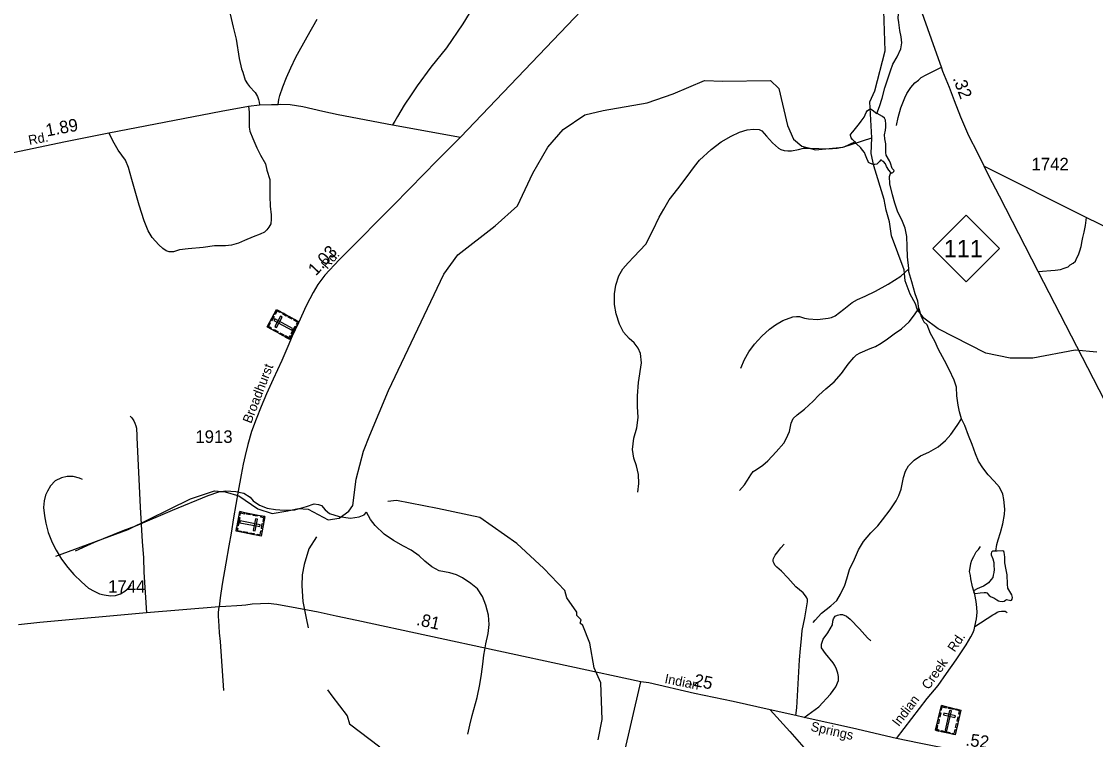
# Model space of a CAD drawing. Extents: x 2206922 to 2357709, y 510027 to 673830.
# Drawn here: x 2317208 to 2327936, y 539926 to 547095 of the extents above; entities that cross this region are included whole.
import ezdxf

# ---------------------------------------------------------------- set-up
doc = ezdxf.new("R2010")
doc.units = 0
for name, color, linetype in [('Exist Cultural Cemetery CELL', 7, 'Continuous'), ('Exist Hydrographic Creek Single Shore', 7, 'Continuous'), ('Exist Hydrographic Misc Water Feature', 7, 'Continuous'), ('Exist Hydrographic Pond Under 1500 Sq Ft', 7, 'Continuous'), ('Exist Road Non-System Type 51', 7, 'Continuous'), ('Exist Road Non-System Type 51 Label', 7, 'Continuous'), ('Exist Road Primary NC Attributed', 7, 'Continuous'), ('Exist Road Primary NC Service Mileage Hundredths English Label', 7, 'Continuous'), ('Exist Road Primary NC Shield CELL', 7, 'Continuous'), ('Exist Road Primary NC Shield Number Label', 7, 'Continuous'), ('Exist Road Secondary Mileage Hundredths English Label', 7, 'Continuous'), ('Exist Road Secondary Type 51 Attributed', 7, 'Continuous'), ('Exist Road Secondary Type 51 Label', 7, 'Continuous'), ('Exist Road Secondary Type 51 Number Label', 7, 'Continuous')]:
    doc.layers.add(name, color=color, linetype=linetype)

msp = doc.modelspace()

# ---------------------------------------------------------------- linework, layer by layer
at = {"layer": 'Exist Cultural Cemetery CELL'}
for points in [[(2319661, 544046), (2319757, 544220), (2319980, 544098), (2319884, 543923)], [(2319696, 544111), (2319721, 544156), (2319731, 544151), (2319706, 544105)], [(2319795, 544199), (2319789, 544190), (2319761, 544205), (2319741, 544170), (2319732, 544175), (2319757, 544220)], [(2319740, 544049), (2319756, 544040), (2319813, 544143), (2319797, 544152)], [(2319853, 544154), (2319815, 544175), (2319821, 544185), (2319859, 544164)], [(2319911, 544122), (2319873, 544143), (2319878, 544153), (2319916, 544132)], [(2319699, 544025), (2319704, 544035), (2319676, 544050), (2319695, 544086), (2319686, 544091), (2319661, 544046)], [(2319739, 544127), (2319730, 544111), (2319907, 544013), (2319916, 544030)], [(2319901, 543979), (2319942, 544053), (2319952, 544048), (2319911, 543974)], [(2319964, 544069), (2319954, 544074), (2319964, 544093), (2319929, 544113), (2319934, 544123), (2319980, 544098)], [(2319764, 543989), (2319726, 544010), (2319731, 544020), (2319769, 543999)], [(2319822, 543957), (2319784, 543978), (2319790, 543988), (2319828, 543967)], [(2319900, 543952), (2319890, 543958), (2319879, 543938), (2319844, 543958), (2319838, 543948), (2319884, 543923)], [(2319638, 542153), (2319601, 541958), (2319351, 542005), (2319388, 542201)], [(2319382, 542168), (2319393, 542166), (2319397, 542188), (2319437, 542180), (2319439, 542191), (2319388, 542201)], [(2319389, 542142), (2319373, 542059), (2319362, 542061), (2319378, 542144)], [(2319589, 542052), (2319593, 542070), (2319394, 542108), (2319390, 542089)], [(2319457, 542188), (2319499, 542180), (2319497, 542168), (2319455, 542176)], [(2319523, 542175), (2319566, 542167), (2319563, 542156), (2319521, 542164)], [(2319564, 542126), (2319546, 542129), (2319524, 542014), (2319542, 542010)], [(2319596, 542161), (2319594, 542150), (2319625, 542144), (2319618, 542104), (2319629, 542102), (2319638, 542153)], [(2319357, 542038), (2319369, 542035), (2319364, 542014), (2319404, 542006), (2319402, 541995), (2319351, 542005)], [(2319424, 542003), (2319467, 541995), (2319465, 541984), (2319422, 541992)], [(2319489, 541990), (2319532, 541982), (2319529, 541971), (2319487, 541979)], [(2319559, 541966), (2319561, 541977), (2319592, 541971), (2319600, 542011), (2319611, 542009), (2319601, 541958)], [(2319625, 542080), (2319615, 542030), (2319604, 542032), (2319613, 542083)], [(2326398, 540265), (2326592, 540220), (2326533, 539972), (2326339, 540018)], [(2326371, 540151), (2326381, 540193), (2326392, 540191), (2326382, 540148)], [(2326388, 540223), (2326399, 540221), (2326406, 540252), (2326446, 540243), (2326448, 540253), (2326398, 540265)], [(2326422, 540190), (2326418, 540172), (2326532, 540145), (2326537, 540163)], [(2326497, 540212), (2326479, 540216), (2326433, 540019), (2326451, 540014)], [(2326470, 540248), (2326520, 540236), (2326518, 540225), (2326467, 540237)], [(2326582, 540178), (2326571, 540180), (2326578, 540211), (2326539, 540221), (2326541, 540232), (2326592, 540220)], [(2326372, 540010), (2326374, 540021), (2326353, 540026), (2326362, 540066), (2326351, 540068), (2326339, 540018)], [(2326355, 540086), (2326365, 540128), (2326376, 540125), (2326367, 540083)], [(2326539, 540045), (2326549, 540087), (2326560, 540084), (2326550, 540042)], [(2326554, 540109), (2326564, 540151), (2326575, 540149), (2326565, 540106)], [(2326398, 540016), (2326481, 539996), (2326478, 539985), (2326395, 540004)], [(2326501, 539979), (2326504, 539991), (2326525, 539986), (2326534, 540025), (2326545, 540022), (2326533, 539972)]]:
    msp.add_lwpolyline(points, close=True, dxfattribs=at)
at = {"layer": 'Exist Hydrographic Creek Single Shore'}
for points in [[(2325703, 545935), (2325682, 546292), (2325731, 546402), (2325835, 546803), (2325822, 547203), (2325779, 547418), (2325769, 547575), (2325732, 547768)], [(2317552, 541757), (2318274, 542022), (2318895, 542329), (2319136, 542408), (2319244, 542399), (2319378, 542359), (2319570, 542229), (2319713, 542182), (2319870, 542208), (2319971, 542232), (2320071, 542226), (2320272, 542119), (2320380, 542137), (2320478, 542206), (2320519, 542264), (2320550, 542524), (2320623, 542806), (2320688, 542966), (2320874, 543410), (2321427, 544574), (2321567, 544767), (2321939, 545054), (2322162, 545254), (2322317, 545582), (2322464, 545840), (2322620, 546017), (2322835, 546164), (2323018, 546207), (2323458, 546284), (2323716, 546373), (2324031, 546507), (2324214, 546501), (2324689, 546507), (2324773, 546426), (2324860, 546058), (2324920, 545920), (2325004, 545851), (2325138, 545813), (2325412, 545841), (2325703, 545935)], [(2327950, 543794), (2327733, 543815), (2327309, 543735), (2327084, 543733), (2326842, 543782), (2326365, 544025), (2326222, 544134), (2326154, 544224), (2326137, 544275), (2326086, 544372), (2326035, 544507), (2326025, 544615), (2325897, 544955), (2325879, 545095), (2325844, 545212), (2325826, 545319), (2325723, 545653), (2325696, 545777), (2325703, 545935)]]:
    msp.add_lwpolyline(points, dxfattribs=at)
at = {"layer": 'Exist Hydrographic Misc Water Feature'}
for points in [[(2325752, 546176), (2325779, 546248), (2325804, 546329), (2325831, 546433), (2325864, 546533), (2325889, 546603), (2325912, 546668), (2325956, 546744), (2325993, 546823), (2326000, 546883), (2325996, 546941), (2325983, 547005), (2325970, 547084), (2325965, 547128), (2325970, 547216), (2325978, 547308), (2325979, 547378), (2325984, 547450), (2325993, 547528), (2325991, 547598), (2325968, 547660), (2325925, 547721), (2325895, 547765)], [(2325531, 545894), (2325509, 545918), (2325495, 545934), (2325488, 545956), (2325490, 545966), (2325512, 545992), (2325579, 546078), (2325597, 546099), (2325626, 546141), (2325646, 546185), (2325660, 546205), (2325676, 546217), (2325687, 546222), (2325705, 546214), (2325752, 546176)], [(2325892, 545586), (2325900, 545582), (2325912, 545586), (2325918, 545593), (2325922, 545598), (2325924, 545608), (2325916, 545618), (2325906, 545628), (2325889, 545682), (2325879, 545704), (2325846, 545762), (2325842, 545787), (2325841, 545873), (2325831, 545923), (2325830, 545963), (2325838, 546009), (2325841, 546039), (2325841, 546071), (2325837, 546111), (2325829, 546129), (2325810, 546145), (2325756, 546176), (2325752, 546176)], [(2323366, 542396), (2323373, 542481), (2323372, 542571), (2323351, 542658), (2323325, 542736), (2323311, 542822), (2323324, 542934), (2323355, 543038), (2323368, 543140), (2323361, 543250), (2323360, 543358), (2323372, 543492), (2323402, 543688), (2323391, 543780), (2323369, 543832), (2323328, 543888), (2323277, 543931), (2323223, 543992), (2323180, 544072), (2323147, 544175), (2323132, 544271), (2323133, 544375), (2323146, 544463), (2323175, 544555), (2323214, 544626), (2323267, 544686), (2323326, 544745), (2323443, 544872), (2323514, 545007), (2323578, 545141), (2323624, 545222), (2323678, 545316), (2323763, 545425), (2323858, 545546), (2323929, 545647), (2323980, 545711), (2324097, 545817), (2324198, 545894), (2324297, 545949), (2324381, 545990), (2324456, 546014), (2324519, 546021), (2324576, 546018), (2324604, 546002), (2324651, 545951), (2324709, 545883), (2324770, 545830), (2324794, 545818), (2324826, 545807), (2324864, 545805), (2324900, 545805), (2324968, 545818), (2325018, 545829)], [(2325018, 545829), (2325028, 545829), (2325086, 545831), (2325174, 545826), (2325266, 545825), (2325356, 545830), (2325424, 545845), (2325531, 545894)], [(2325892, 545586), (2325872, 545610), (2325850, 545647), (2325840, 545673), (2325819, 545697), (2325809, 545701), (2325799, 545709), (2325787, 545711), (2325781, 545701), (2325761, 545679), (2325751, 545672), (2325733, 545666), (2325715, 545666), (2325689, 545678), (2325676, 545684), (2325669, 545688), (2325665, 545696), (2325653, 545727), (2325638, 545761), (2325628, 545787), (2325610, 545811), (2325593, 545835), (2325547, 545878), (2325535, 545892), (2325531, 545894)], [(2326070, 544624), (2326071, 544630), (2326059, 544744), (2326056, 544850), (2326051, 544950), (2326036, 545032), (2326007, 545099), (2325958, 545201), (2325933, 545282), (2325909, 545364), (2325883, 545474), (2325877, 545548), (2325892, 545586)], [(2324392, 543635), (2324431, 543719), (2324472, 543796), (2324531, 543872), (2324603, 543953), (2324681, 544022), (2324741, 544067), (2324812, 544109), (2324914, 544146), (2324948, 544151), (2324980, 544149), (2325028, 544134), (2325071, 544128), (2325160, 544121), (2325266, 544132), (2325300, 544141), (2325336, 544157), (2325421, 544222), (2325504, 544289), (2325560, 544319), (2325637, 544354), (2325739, 544403), (2325865, 544473), (2325993, 544552), (2326070, 544624)], [(2326173, 544230), (2326162, 544304), (2326135, 544377), (2326100, 544497), (2326071, 544595), (2326070, 544624)], [(2324379, 542413), (2324429, 542468), (2324460, 542516), (2324494, 542569), (2324515, 542601), (2324551, 542623), (2324612, 542664), (2324662, 542708), (2324747, 542797), (2324822, 542884), (2324847, 542928), (2324881, 543001), (2324896, 543085), (2324917, 543131), (2324955, 543169), (2325028, 543224), (2325117, 543305), (2325171, 543363), (2325242, 543428), (2325327, 543497), (2325398, 543582), (2325465, 543675), (2325522, 543741), (2325548, 543768), (2325584, 543788), (2325684, 543829), (2325737, 543851), (2325795, 543882), (2325858, 543926), (2325926, 543975), (2325997, 544028), (2326074, 544095), (2326127, 544165), (2326173, 544230)], [(2326173, 544230), (2326196, 544148), (2326222, 544098), (2326254, 544067)], [(2326596, 543127), (2326576, 543197), (2326563, 543265), (2326552, 543357), (2326547, 543445), (2326526, 543514), (2326473, 543621), (2326428, 543711), (2326369, 543820), (2326332, 543902), (2326287, 543981), (2326254, 544067)], [(2325117, 541096), (2325135, 541118), (2325200, 541187), (2325291, 541260), (2325351, 541314), (2325390, 541377), (2325433, 541467), (2325452, 541531), (2325479, 541624), (2325528, 541728), (2325569, 541821), (2325618, 541903), (2325693, 541988), (2325762, 542059), (2325808, 542119), (2325884, 542220), (2325946, 542308), (2325973, 542363), (2325994, 542425), (2326019, 542541), (2326039, 542607), (2326068, 542659), (2326125, 542716), (2326187, 542759), (2326270, 542796), (2326364, 542849), (2326437, 542913), (2326492, 542970), (2326555, 543063), (2326596, 543127)], [(2326942, 541805), (2326950, 541873), (2326963, 541920), (2326988, 541994), (2327009, 542080), (2327028, 542174), (2327032, 542226), (2327021, 542322), (2327010, 542376), (2326977, 542445), (2326923, 542507), (2326863, 542570), (2326810, 542637), (2326767, 542705), (2326738, 542777), (2326703, 542870), (2326668, 542960), (2326631, 543060), (2326596, 543127)], [(2317818, 542523), (2317789, 542536), (2317723, 542553), (2317665, 542553), (2317608, 542538), (2317546, 542509), (2317498, 542459), (2317469, 542407), (2317449, 542365), (2317434, 542309), (2317429, 542242), (2317438, 542161), (2317450, 542085), (2317476, 541993), (2317516, 541893), (2317555, 541816), (2317608, 541727), (2317671, 541644), (2317732, 541574), (2317807, 541499), (2317877, 541436), (2317934, 541407), (2317986, 541381), (2318034, 541372), (2318096, 541362), (2318146, 541365), (2318196, 541381), (2318242, 541408), (2318281, 541440), (2318303, 541466)], [(2317749, 541810), (2317936, 541898), (2318223, 542013), (2318350, 542060), (2318716, 542215), (2319074, 542364), (2319178, 542399), (2319250, 542410), (2319350, 542403), (2319428, 542386), (2319494, 542345), (2319521, 542309), (2319585, 542266), (2319663, 542237), (2319744, 542222), (2319832, 542217), (2319940, 542220), (2320055, 542253), (2320131, 542278), (2320175, 542272), (2320205, 542261), (2320242, 542219), (2320284, 542183), (2320380, 542152), (2320494, 542136), (2320582, 542151), (2320632, 542171), (2320654, 542197)], [(2321667, 539979), (2321686, 540070), (2321709, 540166), (2321761, 540346), (2321788, 540475), (2321802, 540579), (2321817, 540677), (2321828, 540767), (2321838, 540823), (2321847, 540881), (2321870, 540985), (2321879, 541075), (2321872, 541169), (2321847, 541269), (2321812, 541354), (2321763, 541430), (2321695, 541483), (2321614, 541542), (2321554, 541569), (2321487, 541591), (2321379, 541611), (2321307, 541651), (2321237, 541708), (2321180, 541761), (2321099, 541816), (2321025, 541855), (2320924, 541912), (2320830, 541977), (2320741, 542064), (2320693, 542122), (2320654, 542197)], [(2320156, 541950), (2320080, 541831), (2320032, 541675), (2320013, 541569), (2320010, 541459), (2320019, 541303), (2320051, 541139), (2320072, 541040)], [(2326942, 541805), (2326906, 541805), (2326897, 541797), (2326893, 541783), (2326893, 541771), (2326911, 541731), (2326920, 541695), (2326922, 541665), (2326923, 541623), (2326919, 541595), (2326915, 541567), (2326910, 541543), (2326894, 541523), (2326866, 541491), (2326854, 541481), (2326819, 541458), (2326776, 541442), (2326755, 541432), (2326725, 541413), (2326719, 541401), (2326723, 541391), (2326733, 541385), (2326783, 541392), (2326825, 541394), (2326839, 541395), (2326851, 541391), (2326875, 541363), (2326895, 541349), (2326921, 541340), (2326950, 541322), (2326966, 541312), (2326982, 541308), (2327004, 541304), (2327024, 541307), (2327036, 541319), (2327046, 541323), (2327062, 541321), (2327078, 541317), (2327090, 541315), (2327098, 541318), (2327104, 541328), (2327106, 541343), (2327103, 541357), (2327099, 541371), (2327079, 541405), (2327062, 541437), (2327058, 541477), (2327053, 541569), (2327045, 541619), (2327032, 541690), (2327031, 541746), (2327027, 541772), (2327023, 541794), (2327019, 541804), (2327012, 541810), (2326954, 541807), (2326942, 541805)]]:
    msp.add_lwpolyline(points, dxfattribs=at)
at = {"layer": 'Exist Hydrographic Pond Under 1500 Sq Ft'}
for points in [[(2322969, 539924), (2323009, 540126), (2322996, 540493), (2322928, 540641), (2322884, 540889), (2322815, 541063), (2322790, 541088), (2322798, 541122), (2322756, 541163), (2322756, 541199), (2322654, 541339), (2322637, 541414), (2322426, 541635), (2322157, 541883), (2321788, 542144), (2321362, 542232), (2320953, 542311), (2320869, 542301)], [(2320265, 540422), (2320307, 540362), (2320460, 540164), (2320485, 540083), (2320787, 539853)]]:
    msp.add_lwpolyline(points, dxfattribs=at)
at = {"layer": 'Exist Road Non-System Type 51'}
for points in [[(2319181, 548304), (2319229, 547748), (2319239, 547499), (2319261, 547353), (2319270, 547265), (2319293, 547170), (2319324, 547040), (2319352, 546918), (2319381, 546726), (2319407, 546622), (2319414, 546605), (2319419, 546588), (2319441, 546511), (2319465, 546473), (2319485, 546446), (2319541, 546385), (2319567, 546345), (2319576, 546317), (2319581, 546290), (2319586, 546262)], [(2321754, 547294), (2321617, 547071), (2321455, 546833), (2321296, 546638), (2321161, 546453), (2321099, 546364), (2321031, 546260), (2320965, 546148), (2320938, 546101), (2320914, 546064)], [(2319771, 546268), (2319780, 546316), (2319789, 546357), (2319818, 546444), (2319855, 546537), (2319898, 546632), (2319950, 546738), (2320063, 546943), (2320160, 547118)], [(2325949, 546056), (2325965, 546138), (2325992, 546232), (2326031, 546333), (2326050, 546377), (2326091, 546435), (2326131, 546482), (2326169, 546510), (2326196, 546536), (2326244, 546561), (2326290, 546585), (2326399, 546638)], [(2319475, 546250), (2319481, 546189), (2319481, 546118), (2319481, 546068), (2319481, 546040), (2319488, 545999), (2319519, 545926), (2319559, 545833), (2319597, 545759), (2319645, 545673), (2319660, 545610), (2319688, 545517), (2319688, 545451), (2319688, 545350), (2319693, 545251), (2319703, 545165), (2319703, 545122), (2319698, 545074), (2319680, 545042), (2319658, 545016), (2319635, 544991), (2319592, 544971), (2319524, 544946), (2319435, 544908), (2319377, 544882), (2319307, 544862), (2319246, 544855), (2319135, 544855), (2319024, 544839), (2318872, 544824), (2318786, 544814), (2318756, 544804), (2318728, 544796), (2318683, 544796), (2318652, 544804), (2318620, 544829), (2318579, 544865), (2318514, 544940), (2318473, 545004), (2318435, 545105), (2318385, 545261), (2318311, 545517), (2318276, 545638), (2318248, 545709), (2318175, 545810), (2318122, 545903), (2318102, 545946), (2318082, 545982)], [(2327362, 544600), (2327534, 544612), (2327588, 544618), (2327624, 544633), (2327662, 544647), (2327684, 544665), (2327713, 544682), (2327735, 544702), (2327749, 544734), (2327767, 544764), (2327778, 544806), (2327792, 544850), (2327803, 544904), (2327809, 544940), (2327822, 544991), (2327835, 545057), (2327846, 545139)], [(2318293, 543155), (2318309, 543139), (2318329, 543109), (2318341, 543084), (2318352, 543058), (2318356, 543034), (2318356, 543006), (2318360, 542988), (2318361, 542942), (2318394, 542245), (2318414, 541903), (2318426, 541741), (2318430, 541597), (2318458, 541192)], [(2324942, 540166), (2324952, 540244), (2324979, 540720), (2324988, 540836), (2324998, 540930), (2325007, 541013), (2325032, 541142), (2325052, 541262), (2325060, 541302), (2325058, 541324), (2325053, 541340), (2325041, 541359), (2325016, 541389), (2324942, 541452), (2324862, 541542), (2324799, 541607), (2324752, 541646), (2324734, 541666), (2324725, 541685), (2324717, 541702), (2324717, 541719), (2324720, 541734), (2324735, 541766), (2324762, 541800), (2324794, 541840), (2324826, 541877)], [(2326731, 541055), (2326748, 541131), (2326754, 541193), (2326751, 541243), (2326744, 541303), (2326732, 541375), (2326707, 541451), (2326690, 541532), (2326688, 541564), (2326679, 541602), (2326683, 541640), (2326690, 541682), (2326700, 541716), (2326720, 541754), (2326743, 541799), (2326767, 541823), (2326788, 541853)], [(2319230, 540416), (2319197, 540904), (2319187, 540990), (2319184, 541058), (2319180, 541112), (2319177, 541156), (2319177, 541194), (2319183, 541250)], [(2325027, 540147), (2325172, 540251), (2325290, 540380), (2325343, 540452), (2325369, 540514), (2325369, 540554), (2325361, 540590), (2325349, 540629), (2325331, 540666), (2325315, 540691), (2325238, 540784), (2325199, 540843), (2325198, 540877), (2325215, 540928), (2325264, 540991), (2325308, 541070), (2325313, 541108), (2325319, 541132), (2325336, 541158), (2325359, 541169), (2325384, 541174), (2325409, 541174), (2325449, 541158), (2325487, 541128), (2325578, 541030), (2325659, 540941), (2325691, 540911)], [(2326731, 541055), (2326910, 541171), (2326931, 541181), (2326955, 541199), (2326973, 541204), (2326997, 541206), (2327015, 541208), (2327033, 541208), (2327055, 541195)], [(2325947, 539937), (2326253, 540334), (2326364, 540465), (2326448, 540586), (2326543, 540723), (2326643, 540872), (2326692, 540951), (2326710, 540989), (2326723, 541021), (2326731, 541055)]]:
    msp.add_lwpolyline(points, dxfattribs=at)
at = {"layer": 'Exist Road Primary NC Attributed'}
for points in [[(2326825, 545650), (2326762, 545779), (2326670, 545954), (2326592, 546141), (2326527, 546302), (2326477, 546435), (2326412, 546596), (2326399, 546638), (2326335, 546816), (2326188, 547229)], [(2328736, 541917), (2328193, 542992), (2327362, 544600), (2326977, 545351), (2326872, 545554), (2326825, 545650)]]:
    msp.add_lwpolyline(points, dxfattribs=at)
at = {"layer": 'Exist Road Primary NC Shield CELL'}
msp.add_lwpolyline([(2326311, 544830), (2326644, 545163), (2326977, 544830), (2326644, 544497)], close=True, dxfattribs=at)
at = {"layer": 'Exist Road Secondary Type 51 Attributed'}
for points in [[(2325185, 550826), (2325127, 550648), (2325122, 550633), (2325044, 550436), (2324919, 550096), (2324786, 549758), (2324523, 549115), (2324348, 548731), (2324256, 548522), (2324195, 548426), (2324124, 548330), (2324056, 548269), (2323981, 548202), (2323883, 548136), (2323784, 548086), (2323681, 548040), (2323593, 547995), (2323530, 547955), (2323475, 547909), (2323371, 547803), (2321593, 545939)], [(2316616, 545681), (2317649, 545898), (2318082, 545982), (2319203, 546200), (2319475, 546250), (2319586, 546262), (2319707, 546267), (2319771, 546268), (2319799, 546269), (2319893, 546265), (2320018, 546245), (2320217, 546201), (2320373, 546168), (2320914, 546064), (2321593, 545939)], [(2321593, 545939), (2321365, 545709), (2321221, 545563), (2321089, 545432), (2320913, 545250), (2320764, 545101), (2320596, 544929), (2320381, 544714), (2320239, 544562), (2320167, 544468), (2320121, 544388), (2320087, 544325), (2320050, 544250), (2320021, 544188), (2319974, 544086), (2319913, 543952), (2319868, 543849), (2319810, 543711), (2319721, 543523), (2319657, 543378), (2319601, 543252), (2319553, 543126), (2319507, 543003), (2319469, 542870), (2319441, 542763), (2319422, 542676), (2319403, 542568), (2319372, 542406), (2319350, 542271), (2319325, 542141), (2319302, 541985), (2319278, 541860), (2319248, 541686), (2319212, 541478), (2319192, 541340), (2319183, 541250)], [(2326825, 545650), (2327846, 545139), (2328564, 544789), (2328690, 544732), (2328765, 544687), (2328821, 544654), (2328896, 544606), (2328986, 544550), (2329056, 544505), (2329129, 544450), (2329186, 544392), (2329246, 544314), (2329327, 544202), (2329503, 543920), (2329704, 543619), (2329999, 543251), (2330253, 542932), (2330281, 542888), (2330334, 542807), (2330381, 542736), (2330407, 542674), (2330432, 542603), (2330459, 542525), (2330473, 542445)], [(2319183, 541250), (2318458, 541192), (2317390, 541093), (2317177, 541070)], [(2323395, 540503), (2320557, 541114), (2320351, 541158), (2320173, 541196), (2320065, 541217), (2319960, 541238), (2319758, 541274), (2319673, 541283), (2319596, 541281), (2319513, 541276), (2319448, 541269), (2319409, 541265), (2319359, 541261), (2319251, 541254), (2319183, 541250)], [(2322793, 537900), (2323395, 540503)], [(2324685, 540223), (2324318, 540304), (2323929, 540385), (2323473, 540491), (2323395, 540503)], [(2324685, 540223), (2324882, 540006), (2325023, 539847), (2325151, 539716), (2325264, 539593), (2325530, 539359), (2325618, 539290), (2325714, 539206), (2325788, 539151), (2325856, 539100), (2325969, 539014), (2326124, 538893), (2326335, 538725), (2326576, 538539), (2326632, 538495)], [(2327406, 539803), (2327343, 539794), (2327190, 539783), (2327028, 539776), (2326939, 539783), (2326754, 539796), (2326612, 539810), (2326486, 539830), (2326342, 539855), (2326176, 539890), (2325947, 539937), (2325510, 540040), (2325027, 540147), (2324942, 540166), (2324685, 540223)]]:
    msp.add_lwpolyline(points, dxfattribs=at)

# ---------------------------------------------------------------- texts
at = {"layer": 'Exist Road Non-System Type 51 Label'}
for s, rotation, p in [('Rd.', 56.0448, (2326530, 540792)), ('Creek', 55.0939, (2326270, 540417)), ('Indian', 52.4028, (2325971, 540049))]:
    msp.add_text(s, height=95, rotation=rotation, dxfattribs=at).set_placement(p)
at = {"layer": 'Exist Road Primary NC Service Mileage Hundredths English Label'}
msp.add_text('.32', height=125, rotation=290.3959, dxfattribs=at).set_placement((2326509, 546528))
at = {"layer": 'Exist Road Primary NC Shield Number Label'}
msp.add_text('111', height=175, dxfattribs=at).set_placement((2326420, 544740))
at = {"layer": 'Exist Road Secondary Mileage Hundredths English Label'}
for s, rotation, p in [('1.89', 10.6876, (2317462, 545946)), ('1.03', 47.1012, (2320149, 544550)), ('.81', 347.3874, (2321146, 541071)), ('.25', 348.1947, (2323871, 540472)), ('.52', 352.7293, (2326634, 539866))]:
    msp.add_text(s, height=125, rotation=rotation, dxfattribs=at).set_placement(p)
at = {"layer": 'Exist Road Secondary Type 51 Label'}
for s, rotation, p in [('Rd.', 10.6876, (2317287, 545862)), ('Rd.', 48.857, (2320262, 544616)), ('Broadhurst', 68.9352, (2319502, 543075)), ('Indian', 348.6924, (2323627, 540490)), ('Springs', 347.4735, (2325085, 540014))]:
    msp.add_text(s, height=95, rotation=rotation, dxfattribs=at).set_placement(p)
at = {"layer": 'Exist Road Secondary Type 51 Number Label'}
for s, p in [('1742', (2327297, 545609)), ('1913', (2318945, 542888)), ('1744', (2318074, 541392))]:
    msp.add_text(s, height=125, dxfattribs=at).set_placement(p)

doc.saveas('drawing.dxf')
